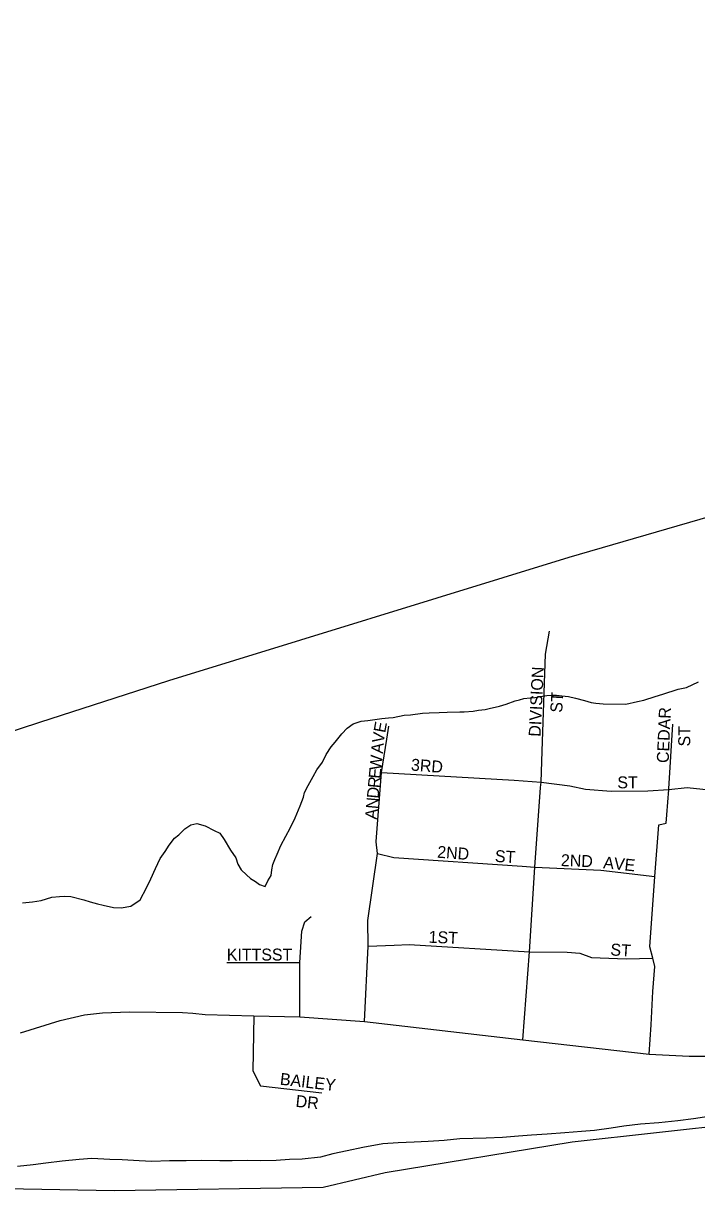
# Model space of a CAD drawing. Extents: x 0 to 34, y 0 to 22.
# Drawn here: x 6.056 to 6.591, y 14.808 to 15.734 of the extents above; entities that cross this region are included whole.
import ezdxf

# ---------------------------------------------------------------- set-up
doc = ezdxf.new("R2010")
doc.units = 0
for name, color, linetype in [('GM_X_County', 7, 'Continuous'), ('GM_X_County_Road', 7, 'Continuous'), ('GM_X_Major_River', 7, 'Continuous'), ('GM_X_Minor_River', 7, 'Continuous'), ('GM_X_Township', 7, 'Continuous'), ('GM_X_Township_ROW', 7, 'Continuous'), ('GM_X_Township_Subdivision', 7, 'Continuous'), ('GM_X_Township_Subdivision_Text', 7, 'Continuous'), ('GM_X_US_Route', 7, 'Continuous')]:
    doc.layers.add(name, color=color, linetype=linetype)

msp = doc.modelspace()

# ---------------------------------------------------------------- linework, layer by layer
at = {"layer": 'GM_X_County'}
msp.add_lwpolyline([(5.81192, 14.81413), (6.12839, 14.80806), (6.29418, 14.8107), (6.34339, 14.82245), (6.49177, 14.84672), (6.62577, 14.8615), (6.85666, 14.90434), (7.30292, 15.01013), (7.36651, 15.03516), (7.82526, 15.188), (8.21322, 15.33138), (8.33283, 15.3731), (8.56485, 15.46794), (8.67596, 15.52844), (8.71954, 15.55584), (8.73927, 15.56156), (8.7787, 15.57074), (8.80562, 15.58596), (8.8602, 15.61489), (8.89736, 15.6271), (8.90844, 15.63)], dxfattribs=at)
at = {"layer": 'GM_X_County_Road'}
msp.add_lwpolyline([(6.05403, 14.93325), (6.08551, 14.943), (6.10485, 14.9475), (6.11902, 14.94907), (6.1404, 14.94998), (6.18269, 14.94953), (6.19078, 14.94885), (6.20046, 14.94773), (6.23928, 14.94679), (6.27579, 14.94602), (6.32691, 14.94217), (6.45259, 14.92788), (6.55305, 14.91648), (6.58485, 14.91492), (6.60306, 14.91492)], dxfattribs=at)
at = {"layer": 'GM_X_Major_River'}
msp.add_lwpolyline([(6.60024, 14.86683), (6.58813, 14.86494), (6.57566, 14.86342), (6.56053, 14.86191), (6.54616, 14.86078), (6.53292, 14.85926), (6.52271, 14.85775), (6.50947, 14.85586), (6.49926, 14.8551), (6.48603, 14.85397), (6.47204, 14.85284), (6.45955, 14.85208), (6.44934, 14.85133), (6.43649, 14.85019), (6.42363, 14.84982), (6.40283, 14.84906), (6.39035, 14.84793), (6.37749, 14.84718), (6.36652, 14.84642), (6.35367, 14.84605), (6.34156, 14.84529), (6.32568, 14.84226), (6.3132, 14.83961), (6.30185, 14.83734), (6.29202, 14.83469), (6.27765, 14.83317), (6.26744, 14.8328), (6.25685, 14.83204), (6.24475, 14.83167), (6.23454, 14.83205), (6.22206, 14.83167), (6.21223, 14.83168), (6.19748, 14.83206), (6.18537, 14.83168), (6.17214, 14.83169), (6.15815, 14.83131), (6.14831, 14.8317), (6.1347, 14.83246), (6.12487, 14.83284), (6.1105, 14.8336), (6.10066, 14.83284), (6.08705, 14.83133), (6.07419, 14.82981), (6.06398, 14.82868), (6.0515, 14.82717)], dxfattribs=at)
at = {"layer": 'GM_X_Minor_River'}
for points in [[(6.53455, 15.19414), (6.54368, 15.19626), (6.54862, 15.19731), (6.55776, 15.2002), (6.56385, 15.20199), (6.57604, 15.20596), (6.58251, 15.20737), (6.59205, 15.21176)], [(6.05563, 15.03637), (6.0636, 15.03737), (6.07044, 15.03839), (6.07881, 15.04091), (6.08489, 15.04156), (6.08906, 15.04187), (6.09398, 15.04141), (6.10416, 15.03896), (6.10943, 15.03735), (6.11509, 15.03573), (6.11961, 15.03452), (6.12792, 15.03286), (6.13397, 15.03238), (6.14157, 15.03377), (6.14886, 15.03896), (6.15395, 15.04836), (6.15748, 15.05552), (6.16104, 15.06381), (6.16497, 15.07172), (6.16885, 15.07735), (6.17197, 15.08223), (6.17623, 15.08785), (6.17969, 15.09045), (6.18432, 15.09531), (6.1893, 15.09826), (6.19386, 15.09933), (6.20065, 15.09769), (6.20778, 15.09377), (6.21229, 15.0918), (6.21561, 15.0868), (6.22077, 15.07836), (6.22483, 15.07222), (6.22663, 15.06725), (6.2292, 15.06265), (6.2333, 15.05878), (6.23666, 15.05569), (6.2404, 15.05335), (6.24377, 15.05101), (6.24829, 15.04941), (6.25026, 15.05394), (6.25299, 15.05807), (6.25344, 15.06262), (6.25428, 15.06678), (6.25586, 15.07093), (6.25783, 15.07507), (6.2606, 15.08186), (6.26452, 15.08939), (6.26804, 15.09578), (6.27198, 15.10407), (6.27593, 15.11349), (6.2787, 15.12028), (6.27953, 15.12407), (6.28228, 15.12972), (6.28619, 15.13686), (6.28931, 15.14213), (6.29359, 15.14813), (6.29672, 15.15415), (6.30062, 15.16016), (6.30371, 15.16391), (6.30913, 15.17065), (6.31338, 15.17513), (6.31798, 15.17847), (6.32446, 15.18064), (6.32978, 15.18131), (6.33699, 15.18232), (6.34079, 15.18264), (6.3461, 15.1833), (6.34989, 15.18362), (6.35864, 15.18537), (6.36357, 15.18566), (6.37306, 15.18702), (6.37837, 15.18731), (6.38633, 15.18755), (6.39277, 15.18783), (6.40262, 15.18804), (6.40603, 15.18798), (6.41324, 15.18861), (6.41742, 15.1893), (6.42273, 15.18997), (6.42692, 15.19104), (6.43072, 15.19173), (6.43414, 15.19244), (6.43948, 15.19424), (6.44672, 15.19678), (6.45014, 15.19748), (6.45357, 15.19856), (6.4585, 15.19923), (6.4623, 15.19955), (6.46685, 15.20023), (6.47179, 15.2009), (6.47558, 15.20122), (6.47937, 15.20116), (6.48353, 15.2007), (6.48882, 15.20023), (6.49448, 15.199), (6.50165, 15.19698), (6.50692, 15.19537), (6.5107, 15.19492), (6.51637, 15.19445), (6.53455, 15.19414)]]:
    msp.add_lwpolyline(points, dxfattribs=at)
at = {"layer": 'GM_X_Township'}
msp.add_lwpolyline([(5.81192, 14.81413), (6.12839, 14.80806), (6.29418, 14.8107), (6.34339, 14.82245), (6.49177, 14.84672), (6.62577, 14.8615), (6.85666, 14.90434), (7.30292, 15.01013), (7.36651, 15.03516), (7.82526, 15.188), (8.21322, 15.33138), (8.33283, 15.3731), (8.56485, 15.46794), (8.67596, 15.52844), (8.71954, 15.55584), (8.73927, 15.56156), (8.7787, 15.57074), (8.80562, 15.58596), (8.8602, 15.61489), (8.89736, 15.6271), (8.90844, 15.63)], dxfattribs=at)
at = {"layer": 'GM_X_Township_ROW'}
for points in [[(6.32691, 14.94217), (6.32987, 15.00203), (6.3296, 15.0224), (6.3374, 15.07563), (6.33637, 15.08497)], [(6.27629, 14.99744), (6.27733, 15.01406), (6.27964, 15.02137), (6.28464, 15.0256)]]:
    msp.add_lwpolyline(points, dxfattribs=at)
at = {"layer": 'GM_X_Township_Subdivision'}
for points in [[(6.46799, 15.15674), (6.47071, 15.2338), (6.47375, 15.25202)], [(6.34469, 15.1665), (6.34624, 15.17663)], [(6.56853, 15.12694), (6.57178, 15.17825)], [(6.33637, 15.08497), (6.33635, 15.08509), (6.34065, 15.14003), (6.34469, 15.1665)], [(6.46682, 15.12809), (6.46713, 15.13233), (6.46799, 15.15674)], [(6.34065, 15.14003), (6.44593, 15.13373), (6.46713, 15.13233), (6.49, 15.12937), (6.50238, 15.12676), (6.52289, 15.12513), (6.55188, 15.12546), (6.5685, 15.12638), (6.58315, 15.12807), (6.59556, 15.12663), (6.63045, 15.12287)], [(6.45259, 14.92788), (6.45802, 14.99768), (6.46214, 15.06477), (6.46682, 15.12809)], [(6.56698, 15.10644), (6.5685, 15.12638), (6.56853, 15.12694)], [(6.55305, 14.91648), (6.55468, 14.93956), (6.55576, 14.96617), (6.55739, 14.986), (6.55576, 14.99252), (6.55344, 15.00169), (6.5576, 15.05737), (6.56065, 15.09828), (6.56647, 15.09981), (6.56698, 15.10644)], [(6.3374, 15.07563), (6.35036, 15.07248), (6.45218, 15.06545)], [(6.45218, 15.06545), (6.46214, 15.06477), (6.5147, 15.06231), (6.5576, 15.05737)], [(6.32987, 15.00203), (6.35047, 15.00288)], [(6.35047, 15.00288), (6.36245, 15.00338), (6.45802, 14.99768), (6.48789, 14.99741), (6.49793, 14.99659), (6.50716, 14.99306), (6.53459, 14.99197), (6.55576, 14.99252)], [(6.27579, 14.94602), (6.27576, 14.98907), (6.27629, 14.99744)], [(6.2177, 14.98908), (6.27576, 14.98907)], [(6.23928, 14.94679), (6.23852, 14.90314), (6.24458, 14.89137), (6.29306, 14.88566)]]:
    msp.add_lwpolyline(points, dxfattribs=at)
at = {"layer": 'GM_X_US_Route'}
for points in [[(6.06926, 15.17982), (6.17161, 15.21295), (6.48951, 15.31069), (6.63625, 15.35347), (6.85428, 15.40737), (6.9758, 15.43872), (7.13959, 15.47493), (7.32779, 15.51719), (7.48111, 15.55316), (7.56574, 15.57231), (7.56968, 15.57321), (7.66601, 15.59649), (7.73616, 15.61621), (7.92957, 15.69717), (8.00724, 15.73447)], [(5.64877, 15.32493), (5.66791, 15.30772), (5.70507, 15.27429), (5.80555, 15.19018), (5.85501, 15.17645), (5.92406, 15.16212), (5.97748, 15.15821), (6.03872, 15.16994), (6.06926, 15.17982)]]:
    msp.add_lwpolyline(points, dxfattribs=at)

# ---------------------------------------------------------------- texts
at = {"layer": 'GM_X_Township_Subdivision_Text'}
for s, rotation, p in [('DIVISION', 87.22778, (6.46676, 15.16814)), ('ST', 86.42562, (6.48386, 15.18715)), ('CEDAR', 87.56468, (6.56843, 15.1473)), ('E', 79.53249, (6.34344, 15.17099)), ('ST', 90, (6.58555, 15.16056)), ('V', 81.8639, (6.34228, 15.16284)), ('A', 84.80122, (6.34154, 15.15467)), ('W', 84.78781, (6.34033, 15.14139)), ('3RD', 355.60152, (6.36368, 15.1415)), ('E', 84.77457, (6.33972, 15.13475)), ('R', 84.78455, (6.33904, 15.12728)), ('ST', 0.00001, (6.52771, 15.12734)), ('N', 84.77651, (6.33752, 15.11068)), ('D', 84.76908, (6.33828, 15.11898)), ('A', 84.79091, (6.33676, 15.10238)), ('2ND', 355.76347, (6.38451, 15.07233)), ('ST', 356.42324, (6.43032, 15.069)), ('2ND', 357.87884, (6.48277, 15.06567)), ('AVE', 354.09392, (6.51623, 15.06399)), ('1ST', 357.5105, (6.37779, 15.00484)), ('KITTS', 0.00001, (6.21771, 14.99067)), ('ST', 0.00001, (6.25354, 14.99067)), ('ST', 356.18559, (6.52199, 14.99483)), ('BAILEY', 353.29058, (6.25957, 14.89221)), ('DR', 353.99019, (6.27204, 14.87463))]:
    msp.add_text(s, height=0.00947, rotation=rotation, dxfattribs=at).set_placement(p)

doc.saveas('drawing.dxf')
